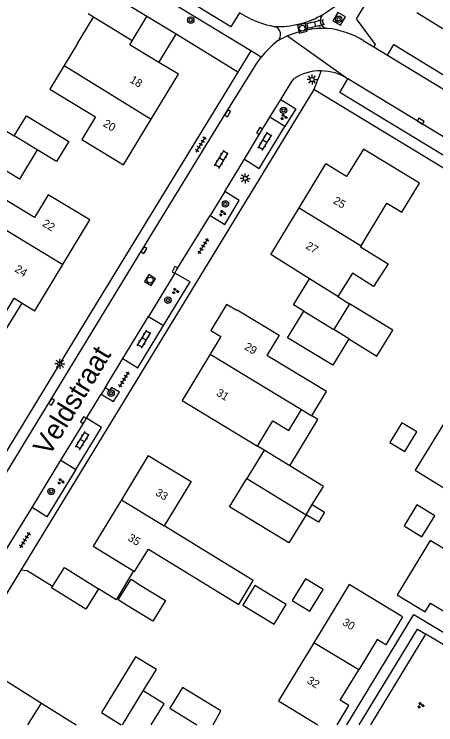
# Model space of a CAD drawing. Extents: x 136000 to 141014, y 402000 to 403500.
# Drawn here: x 137855.5 to 137908.1, y 402000 to 402088.8 of the extents above; entities that cross this region are included whole.
import ezdxf

# ---------------------------------------------------------------- set-up
doc = ezdxf.new("R2010")
doc.units = 0
for name, color, linetype in [('gg-afsc-erfafscheiding', 7, 'Continuous'), ('gg-anno-huisnummerreeks BGT', 7, 'Continuous'), ('gg-anno-openbare ruimte label', 7, 'Continuous'), ('gg-bbg-bijgebouw', 7, 'Continuous'), ('gg-bbg-gedigitaliseerde bebouwing', 7, 'Continuous'), ('gg-bbg-gedigitaliseerde bijgebouw', 7, 'Continuous'), ('gg-bbg-hoofdgebouw', 7, 'Continuous'), ('gg-bbg-luifel en loopbrug', 7, 'Continuous'), ('gg-bbg-tussenscheiding', 7, 'Continuous'), ('gg-knt-verharding', 7, 'Continuous'), ('gg-knt-verharding nz', 7, 'Continuous'), ('gt-grn-groengrens', 7, 'Continuous'), ('gt-grn-weggrens', 7, 'Continuous'), ('gt-symb-boom', 7, 'Continuous'), ('gt-symb-groenvak', 7, 'Continuous'), ('gt-symb-klinker verharding', 7, 'Continuous'), ('gt-symb-kolk', 7, 'Continuous'), ('gt-symb-lichtmast', 7, 'Continuous'), ('gt-symb-rioolschacht', 7, 'Continuous'), ('gt-symb-tegel verharding', 7, 'Continuous')]:
    doc.layers.add(name, color=color, linetype=linetype)

# ---------------------------------------------------------------- blocks, each defined once
blk = doc.blocks.new('gt0-GRVAK')
at = {"layer": 'gt-symb-groenvak'}
for p, q in [((-0.11, 0.189), (-0.228, 0.24)), ((-0.182, 0.153), (0.088, 0.153)), ((-0.091, 0.211), (-0.156, 0.322)), ((-0.047, 0.214), (-0.047, 0.393)), ((-0.004, 0.211), (0.061, 0.322)), ((0.015, 0.189), (0.133, 0.24)), ((0.262, -0.052), (0.197, 0.059)), ((0.305, -0.049), (0.305, 0.13)), ((0.349, -0.052), (0.414, 0.059)), ((-0.245, -0.228), (-0.363, -0.177)), ((-0.318, -0.264), (-0.047, -0.264)), ((-0.226, -0.206), (-0.291, -0.095)), ((-0.183, -0.203), (-0.183, -0.024)), ((-0.139, -0.206), (-0.074, -0.095)), ((-0.12, -0.228), (-0.002, -0.177)), ((0.243, -0.074), (0.125, -0.023)), ((0.17, -0.11), (0.441, -0.11)), ((0.368, -0.074), (0.486, -0.023))]:
    blk.add_line(p, q, dxfattribs=at)
blk = doc.blocks.new('gt0-KOLK')
at = {"layer": 'gt-symb-kolk'}
blk.add_lwpolyline([(0, 0), (0.375, 0), (0.375, 0.4), (-0.375, 0.4), (-0.375, 0), (0, 0)], dxfattribs=at)
blk = doc.blocks.new('gt0-BOOM')
at = {"layer": 'gt-symb-boom'}
for radius in [0.4, 0.2]:
    blk.add_circle((0, 0), radius, dxfattribs=at)
blk = doc.blocks.new('gt0-RS')
at = {"layer": 'gt-symb-rioolschacht'}
blk.add_lwpolyline([(-0.5, -0.5), (0.5, -0.5), (0.5, 0.5), (-0.5, 0.5)], close=True, dxfattribs=at)
blk.add_circle((0, 0), 0.375, dxfattribs=at)
blk = doc.blocks.new('gt0-LMAST')
at = {"layer": 'gt-symb-lichtmast'}
for p, q in [((-0.182, 0.173), (-0.447, 0.438)), ((-0.005, 0.246), (-0.005, 0.621)), ((0.172, 0.173), (0.437, 0.438)), ((-0.255, -0.004), (-0.63, -0.004)), ((-0.182, -0.181), (-0.447, -0.446)), ((-0.005, -0.254), (-0.005, -0.629)), ((0.437, -0.446), (0.172, -0.181)), ((0.245, -0.004), (0.62, -0.004))]:
    blk.add_line(p, q, dxfattribs=at)
blk.add_circle((-0.005, -0.004), 0.25, dxfattribs=at)
blk = doc.blocks.new('gt0-KL1')
at = {"layer": 'gt-symb-klinker verharding'}
for p, q in [((-1.15, 0.3), (1.15, 0.3)), ((-1, -0.3), (-1, 0.3)), ((-0.5, 0.3), (-0.5, 0.45)), ((0, -0.3), (0, 0.3)), ((0.5, 0.3), (0.5, 0.45)), ((1, -0.3), (1, 0.3)), ((-1.15, -0.3), (1.15, -0.3)), ((-0.5, -0.45), (-0.5, -0.3)), ((0.5, -0.45), (0.5, -0.3))]:
    blk.add_line(p, q, dxfattribs=at)
blk = doc.blocks.new('gt0-TEG1')
at = {"layer": 'gt-symb-tegel verharding'}
for p, q in [((-1.125, 0), (1.125, 0)), ((-0.9, -0.25), (-0.9, 0.25)), ((-0.45, -0.25), (-0.45, 0.25)), ((0, -0.25), (0, 0.25)), ((0.45, -0.25), (0.45, 0.25)), ((0.9, -0.25), (0.9, 0.25))]:
    blk.add_line(p, q, dxfattribs=at)

msp = doc.modelspace()

# ---------------------------------------------------------------- linework, layer by layer
at = {"layer": 'gg-afsc-erfafscheiding'}
msp.add_line((137856.318, 402019.331), (137851.395, 402011.282), dxfattribs=at)
for points in [[(137860.259, 402017.274), (137857.104, 402019.249), (137856.318, 402019.331)], [(137870.4, 402019.217), (137868.224, 402015.603), (137865.996, 402016.998)]]:
    msp.add_lwpolyline(points, dxfattribs=at)
at = {"layer": 'gg-bbg-bijgebouw'}
for p, q in [((137872.04, 402088.5), (137866.67, 402091.79)), ((137870.227, 402085.447), (137872.04, 402088.5)), ((137861.745, 402019.648), (137865.996, 402016.998)), ((137866.372, 402001.53), (137868.861, 402000))]:
    msp.add_line(p, q, dxfattribs=at)
msp.add_lwpolyline([(137865.996, 402016.998), (137864.409, 402014.452), (137860.15, 402017.1)], dxfattribs=at)
at = {"layer": 'gg-bbg-gedigitaliseerde bebouwing'}
for p, q in [((137863.395, 402085.105), (137865.401, 402088.402)), ((137863.395, 402085.105), (137861.742, 402082.388)), ((137892.348, 402055.722), (137887.52, 402058.75)), ((137895.898, 402053.497), (137892.348, 402055.722)), ((137876.45, 402040.53), (137885.85, 402034.817)), ((137891.371, 402039.372), (137892.636, 402038.602)), ((137885.333, 402018.009), (137874.201, 402024.842)), ((137883.517, 402015.043), (137885.333, 402018.009))]:
    msp.add_line(p, q, dxfattribs=at)
for points in [[(137861.742, 402082.388), (137859.941, 402079.428), (137865.639, 402075.961)], [(137865.639, 402075.961), (137863.924, 402073.142), (137869.12, 402069.97)], [(137864.92, 402063.07), (137859.742, 402066.205), (137858.02, 402063.373), (137850.649, 402067.855)], [(137902.175, 402057.612), (137900.375, 402054.742), (137897.722, 402056.406), (137895.898, 402053.497)], [(137883.33, 402051.85), (137888.579, 402048.66), (137887.052, 402046.148)], [(137892.636, 402038.602), (137894.479, 402041.631), (137887.052, 402046.148)], [(137885.85, 402034.817), (137887.772, 402037.979), (137889.782, 402036.757), (137891.371, 402039.372)], [(137910, 402039.051), (137905.541, 402031.799), (137911.778, 402027.97)], [(137872.23, 402033.63), (137877.568, 402030.38), (137874.201, 402024.842)], [(137870.523, 402019.142), (137872.24, 402021.947), (137883.517, 402015.043)], [(137903.99, 402013.48), (137897.325, 402017.523), (137892.912, 402010.251)], [(137892.912, 402010.251), (137888.499, 402002.98), (137893.407, 402000)]]:
    msp.add_lwpolyline(points, dxfattribs=at)
at = {"layer": 'gg-bbg-gedigitaliseerde bijgebouw'}
for p, q in [((137865.401, 402088.402), (137864.735, 402088.809)), ((137897.363, 402052.605), (137895.387, 402049.377)), ((137891.652, 402051.691), (137895.387, 402049.377)), ((137886.705, 402034.297), (137884.542, 402030.764)), ((137889.905, 402032.338), (137886.705, 402034.297)), ((137891.932, 402026.244), (137892.715, 402027.523)), ((137860.259, 402017.274), (137861.745, 402019.648)), ((137860.15, 402017.1), (137860.259, 402017.274))]:
    msp.add_line(p, q, dxfattribs=at)
for points in [[(137858.369, 402071.842), (137856.132, 402068.186), (137848.285, 402072.989), (137849.387, 402074.789), (137846.417, 402076.607), (137847.535, 402078.435), (137855.487, 402073.591)], [(137855.487, 402073.591), (137857.025, 402076.103), (137862.292, 402072.879), (137860.761, 402070.377), (137858.369, 402071.842)], [(137897.273, 402048.21), (137900.787, 402046.059), (137902.768, 402049.296), (137897.363, 402052.605)], [(137897.273, 402048.21), (137895.257, 402044.916), (137889.618, 402048.367), (137891.652, 402051.691)], [(137902.407, 402035.261), (137904.263, 402034.125), (137905.77, 402036.585), (137903.913, 402037.722), (137902.407, 402035.261)], [(137892.715, 402027.523), (137894.093, 402029.774), (137889.905, 402032.338)], [(137891.932, 402026.244), (137889.772, 402022.715), (137882.38, 402027.232), (137884.542, 402030.764)], [(137904.173, 402024.857), (137906.398, 402023.495), (137908.001, 402026.114), (137905.776, 402027.476), (137904.173, 402024.857)], [(137870.076, 402018.177), (137871.427, 402017.323), (137874.384, 402015.513), (137872.814, 402012.948), (137869.521, 402014.964), (137868.467, 402015.63), (137870.076, 402018.177)], [(137890.216, 402015.538), (137892.399, 402014.202), (137894.059, 402016.913), (137891.876, 402018.25), (137890.216, 402015.538)], [(137871.607, 402004.228), (137873.24, 402006.897), (137870.633, 402008.492), (137866.372, 402001.53)], [(137872.603, 402000), (137874.214, 402002.632), (137871.607, 402004.228)], [(137880.335, 402000), (137881.29, 402001.728), (137876.484, 402004.67), (137874.901, 402002.084), (137878.305, 402000)]]:
    msp.add_lwpolyline(points, dxfattribs=at)
at = {"layer": 'gg-bbg-hoofdgebouw'}
for p, q in [((137875.992, 402081.271), (137873.562, 402082.745)), ((137872.587, 402075.671), (137875.992, 402081.271)), ((137869.12, 402069.97), (137872.587, 402075.671)), ((137891.069, 402064.587), (137894.42, 402070.1)), ((137887.52, 402058.75), (137891.069, 402064.587)), ((137861.539, 402057.503), (137864.92, 402063.07)), ((137858.04, 402051.74), (137861.539, 402057.503)), ((137856.467, 402052.69), (137858.04, 402051.74)), ((137879.963, 402046.31), (137876.45, 402040.53)), ((137872.23, 402033.63), (137868.872, 402028.114)), ((137868.872, 402028.114), (137865.34, 402022.31)), ((137865.34, 402022.31), (137870.4, 402019.217)), ((137870.4, 402019.217), (137870.523, 402019.142)), ((137853.627, 402006.004), (137858.89, 402002.709)), ((137858.89, 402002.709), (137863.219, 402000))]:
    msp.add_line(p, q, dxfattribs=at)
for points in [[(137905.75, 402088.99), (137911.919, 402085.221), (137911.971, 402085.307), (137915.047, 402083.428), (137918.632, 402089.297), (137915.556, 402091.176), (137915.609, 402091.261), (137909.44, 402095.03)], [(137873.562, 402082.745), (137870.782, 402084.431), (137869.931, 402084.949), (137870.227, 402085.447)], [(137898.8, 402059.851), (137902.037, 402065.191), (137903.895, 402064.065), (137906.091, 402067.688), (137899.114, 402071.918), (137896.985, 402068.502), (137894.42, 402070.1)], [(137898.8, 402059.851), (137898.714, 402059.709), (137902.175, 402057.612)], [(137853.417, 402049.909), (137855.469, 402053.292), (137856.467, 402052.69)], [(137883.33, 402051.85), (137883.268, 402051.747), (137881.994, 402052.522), (137880.019, 402049.273), (137881.293, 402048.498), (137879.963, 402046.31)], [(137914.74, 402018.62), (137907.44, 402023.01), (137903.31, 402016.22), (137906.8, 402014.1), (137907.46, 402015.19), (137911.296, 402012.894)], [(137903.99, 402013.48), (137901.89, 402010), (137900.81, 402010.65), (137898.507, 402006.855)], [(137895.819, 402000), (137897.28, 402002.41), (137896.21, 402003.07), (137898.507, 402006.855)]]:
    msp.add_lwpolyline(points, dxfattribs=at)
at = {"layer": 'gg-bbg-luifel en loopbrug'}
for p, q in [((137875.697, 402086.273), (137872.04, 402088.5)), ((137873.562, 402082.745), (137875.697, 402086.273)), ((137895.898, 402053.497), (137897.363, 402052.605)), ((137886.705, 402034.297), (137885.85, 402034.817))]:
    msp.add_line(p, q, dxfattribs=at)
for points in [[(137891.652, 402051.691), (137890.37, 402052.47), (137892.348, 402055.722)], [(137853.417, 402049.909), (137854.409, 402049.31), (137856.467, 402052.69)], [(137889.905, 402032.338), (137893.421, 402038.124), (137892.636, 402038.602)], [(137892.715, 402027.523), (137894.25, 402026.584), (137893.467, 402025.304), (137891.932, 402026.244)], [(137885.55, 402017.406), (137884.048, 402014.953), (137887.929, 402012.577), (137889.431, 402015.031), (137885.55, 402017.406)]]:
    msp.add_lwpolyline(points, dxfattribs=at)
at = {"layer": 'gg-bbg-tussenscheiding'}
for p, q in [((137870.227, 402085.447), (137865.401, 402088.402)), ((137861.742, 402082.388), (137872.587, 402075.671)), ((137858.369, 402071.842), (137855.487, 402073.591)), ((137848.992, 402065.117), (137861.539, 402057.503)), ((137891.069, 402064.587), (137898.8, 402059.851)), ((137897.273, 402048.21), (137895.387, 402049.377)), ((137879.963, 402046.31), (137891.371, 402039.372)), ((137884.542, 402030.764), (137891.932, 402026.244)), ((137868.872, 402028.114), (137874.201, 402024.842)), ((137898.507, 402006.855), (137892.912, 402010.251)), ((137869.019, 402000), (137871.607, 402004.228)), ((137857.199, 402000), (137858.89, 402002.709))]:
    msp.add_line(p, q, dxfattribs=at)
at = {"layer": 'gg-knt-verharding'}
for p, q in [((137885.036, 402084.188), (137859.155, 402099.963)), ((137884.283, 402088.584), (137883.62, 402088.97)), ((137899.07, 402085.51), (137900.404, 402084.697)), ((137885.036, 402084.188), (137883.425, 402081.556)), ((137900.404, 402084.697), (137902.094, 402083.666)), ((137902.094, 402083.666), (137918.101, 402073.906)), ((137917.664, 402068.223), (137897.17, 402080.69)), ((137919.177, 402063.426), (137892.907, 402079.38)), ((137887.417, 402075.903), (137888.778, 402078.128)), ((137889.3, 402074.753), (137887.417, 402075.903)), ((137881.775, 402066.639), (137884.224, 402070.65)), ((137881.775, 402066.639), (137879.939, 402063.619)), ((137875.558, 402056.442), (137872.25, 402051.022)), ((137872.25, 402051.022), (137874.118, 402049.874)), ((137866.825, 402042.097), (137869.053, 402045.758)), ((137866.825, 402042.097), (137866.356, 402041.326)), ((137864.514, 402038.314), (137866.356, 402041.326)), ((137857.709, 402027.144), (137861.325, 402033.072)), ((137861.325, 402033.072), (137863.17, 402031.901))]:
    msp.add_line(p, q, dxfattribs=at)
for points in [[(137952.579, 402177.206), (137951.84, 402176.01), (137898.17, 402088.19), (137900.57, 402084.98), (137900.404, 402084.697)], [(137883.62, 402088.97), (137882.534, 402087.198), (137855.046, 402104.044)], [(137895.288, 402087.97), (137896.222, 402087.401), (137896.839, 402088.44), (137895.905, 402089.008), (137895.288, 402087.97)], [(137889.613, 402086.061), (137888.965, 402085.762), (137888.342, 402085.427)], [(137839.931, 402007.66), (137849.503, 402023.308), (137859.975, 402040.461), (137871.516, 402059.41), (137881.961, 402076.502), (137885.731, 402082.578), (137886.02, 402082.994), (137886.328, 402083.401)], [(137883.425, 402081.556), (137864.71, 402050.982), (137839.276, 402009.207)], [(137888.778, 402078.128), (137890.136, 402080.363), (137890.428, 402080.735)], [(137917.112, 402066.246), (137896.159, 402078.999), (137897.17, 402080.69)], [(137892.907, 402079.38), (137869.162, 402040.438), (137856.318, 402019.331)], [(137888.778, 402078.128), (137890.658, 402076.977), (137889.3, 402074.753)], [(137884.224, 402070.65), (137886.09, 402069.505), (137889.3, 402074.753)], [(137879.939, 402063.619), (137881.795, 402062.487), (137883.578, 402065.525), (137881.775, 402066.639)], [(137875.558, 402056.442), (137875.722, 402056.747), (137879.939, 402063.619)], [(137874.118, 402049.874), (137877.444, 402055.336), (137875.558, 402056.442)], [(137869.053, 402045.758), (137870.931, 402044.61), (137874.118, 402049.874)], [(137866.356, 402041.326), (137867.902, 402040.384), (137868.614, 402041.549), (137867.632, 402042.143), (137867.402, 402041.786), (137866.825, 402042.097)], [(137863.17, 402031.901), (137866.397, 402037.145), (137864.514, 402038.314)], [(137863.17, 402031.901), (137859.548, 402025.989), (137857.709, 402027.144)], [(137853.65, 402020.516), (137853.756, 402020.728), (137857.709, 402027.144)], [(137897.024, 402000), (137905.4, 402013.78), (137920.674, 402004.633)], [(137898.572, 402000), (137905.83, 402011.96), (137906.903, 402011.319)], [(137915.169, 402005.15), (137915.08, 402005.214), (137915.625, 402006.111), (137906.903, 402011.319)]]:
    msp.add_lwpolyline(points, dxfattribs=at)
for centre, radius, start, end in [((137880.27, 402110.555), 25.791, 302.40923, 319.49413), ((137890.14, 402098.984), 11.936, 240.61174, 259.31351), ((137888.467, 402098.294), 11.052, 267.20065, 300.60056), ((137894.678, 402087.991), 0.983, 126.52469, 263.99103), ((137887.742, 402086.252), 1.02, 306.03925, 79.54219), ((137894.264, 402075.238), 11.78, 88.48774, 113.2559), ((137893.438, 402076.146), 10.927, 58.97398, 84.02616), ((137896.127, 402075.675), 12.478, 128.59728, 141.74309), ((137893.763, 402075.468), 6.234, 89.60576, 122.34326), ((137893.764, 402075.466), 6.236, 56.89712, 89.6169)]:
    msp.add_arc(centre, radius, start, end, dxfattribs=at)
at = {"layer": 'gg-knt-verharding nz'}
msp.add_line((137869.053, 402045.758), (137872.25, 402051.022), dxfattribs=at)
for points in [[(137884.224, 402070.65), (137886.293, 402074.078), (137887.417, 402075.903)], [(137861.325, 402033.072), (137864.283, 402037.954), (137864.514, 402038.314)]]:
    msp.add_lwpolyline(points, dxfattribs=at)
at = {"layer": 'gt-grn-groengrens'}
for p, q in [((137883.425, 402081.556), (137875.697, 402086.273)), ((137900.034, 402000), (137906.903, 402011.319))]:
    msp.add_line(p, q, dxfattribs=at)
msp.add_lwpolyline([(137902.094, 402083.666), (137902.902, 402084.984), (137918.868, 402075.195)], dxfattribs=at)
at = {"layer": 'gt-grn-weggrens'}
for p, q in [((137889.613, 402086.061), (137897.17, 402080.69)), ((137886.328, 402083.401), (137885.036, 402084.188)), ((137893.806, 402081.702), (137892.907, 402079.38))]:
    msp.add_line(p, q, dxfattribs=at)

# ---------------------------------------------------------------- block references
at = {"layer": 'gt-symb-boom'}
for p in [(137877.53, 402088.046), (137896.002, 402088.154), (137889.118, 402076.772), (137881.857, 402065.083), (137874.683, 402053.055), (137867.58, 402041.43), (137860.103, 402029.159)]:
    msp.add_blockref('gt0-BOOM', p, dxfattribs=at)
at = {"layer": 'gt-symb-groenvak'}
for p in [(137889.132, 402075.924), (137881.477, 402063.914), (137875.604, 402054.18), (137861.284, 402030.391), (137906.244, 402002.429)]:
    msp.add_blockref('gt0-GRVAK', p, dxfattribs=at)
at = {"layer": 'gt-symb-klinker verharding'}
for p, rotation in [((137893.058, 402087.505), -166.70041567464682), ((137886.789, 402072.888), 59.07554097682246), ((137881.367, 402070.655), 58.61387523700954), ((137871.71, 402048.175), 58.91827016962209), ((137863.99, 402035.505), 58.07354491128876)]:
    msp.add_blockref('gt0-KL1', p, dxfattribs=dict(at, rotation=rotation))
at = {"layer": 'gt-symb-kolk'}
for p, rotation in [((137881.961, 402076.502), -121.79891282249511), ((137906.134, 402075.239), -31.33720572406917), ((137886.293, 402074.078), 58.86920085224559), ((137871.516, 402059.41), -121.41597875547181), ((137875.722, 402056.747), 61.76909816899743), ((137859.975, 402040.461), -121.33720572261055), ((137864.283, 402037.954), 58.790509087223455)]:
    msp.add_blockref('gt0-KOLK', p, dxfattribs=dict(at, rotation=rotation))
at = {"layer": 'gt-symb-lichtmast'}
for p in [(137892.687, 402080.624), (137884.336, 402068.27), (137861.182, 402045.106)]:
    msp.add_blockref('gt0-LMAST', p, dxfattribs=at)
at = {"layer": 'gt-symb-rioolschacht'}
for p, rotation in [((137891.448, 402087.029), -166.1722049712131), ((137872.45, 402055.559), 57.9460559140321)]:
    msp.add_blockref('gt0-RS', p, dxfattribs=dict(at, rotation=rotation))
at = {"layer": 'gt-symb-tegel verharding'}
for p, rotation in [((137878.793, 402072.503), 58.86920085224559), ((137879.101, 402059.789), 58.53512697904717), ((137869.203, 402043.127), 58.74151468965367), ((137856.83, 402023.066), 58.741514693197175)]:
    msp.add_blockref('gt0-TEG1', p, dxfattribs=dict(at, rotation=rotation))

# ---------------------------------------------------------------- texts
at = {"layer": 'gg-anno-huisnummerreeks BGT'}
for s, p in [('18', (137869.834, 402080.339)), ('20', (137866.503, 402074.861)), ('25', (137895.23, 402065.227)), ('22', (137858.914, 402062.384)), ('27', (137891.8, 402059.586)), ('24', (137855.457, 402056.69)), ('29', (137884.141, 402046.98)), ('31', (137880.636, 402041.212)), ('33', (137873.034, 402028.753)), ('35', (137869.589, 402023.094)), ('30', (137896.372, 402012.544)), ('32', (137891.958, 402005.272))]:
    msp.add_text(s, height=1, rotation=328.7, dxfattribs=at).set_placement(p)
at = {"layer": 'gg-anno-openbare ruimte label'}
msp.add_text('Veldstraat', height=2.5, rotation=58.7, dxfattribs=at).set_placement((137859.843, 402033.442))

doc.saveas('drawing.dxf')
